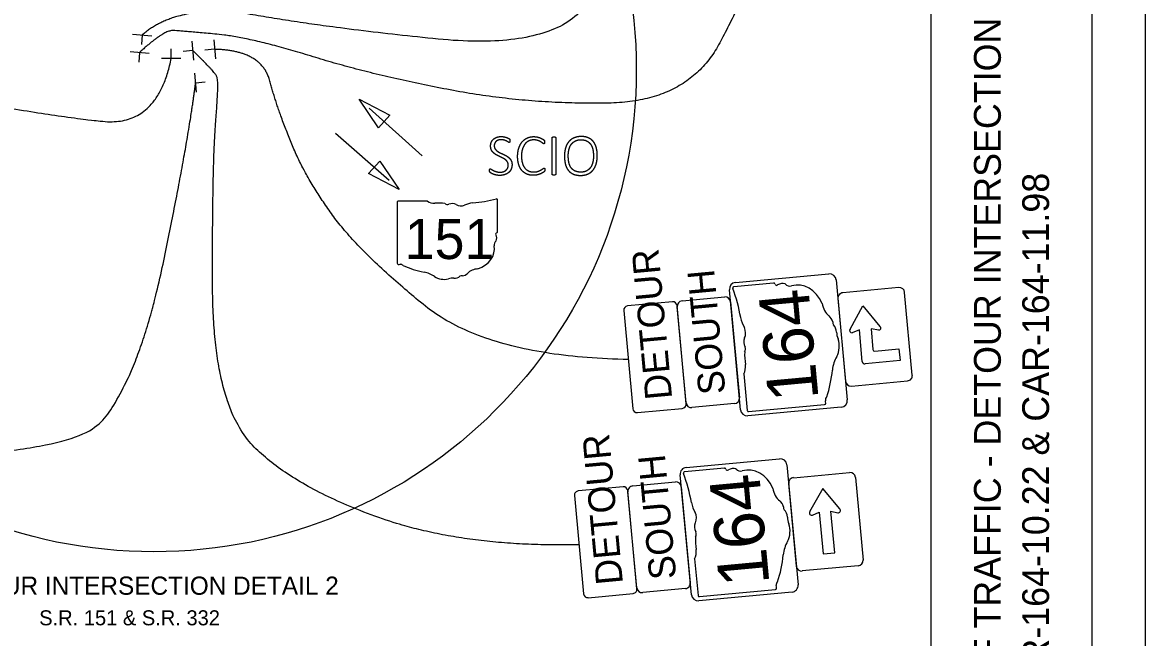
# Model space of a CAD drawing. Extents: x -740 to 1519, y 0 to 440.
# Drawn here: x 470.5 to 680, y 222.2 to 337.1 of the extents above; entities that cross this region are included whole.
import ezdxf

# ---------------------------------------------------------------- set-up
doc = ezdxf.new("R2010")
doc.units = 0
for name, color, linetype in [('Default', 7, 'Continuous'), ('GM_X_County_Road_Text', 7, 'Continuous'), ('GM_X_Major_Lake', 7, 'Continuous'), ('GM_X_Minor_Lake', 7, 'Continuous'), ('GM_X_Minor_River', 7, 'Continuous'), ('GM_X_Section', 7, 'Continuous'), ('SH_Border', 7, 'Continuous'), ('SH_Cut_Line', 7, 'Continuous'), ('SH_Data', 7, 'Continuous')]:
    doc.layers.add(name, color=color, linetype=linetype)

msp = doc.modelspace()

# ---------------------------------------------------------------- linework, layer by layer
at = {"layer": 'Default'}
for p, q in [((535.17, 321.09), (545.07, 312.19)), ((538.91, 307.54), (528.91, 316.31))]:
    msp.add_line(p, q, dxfattribs=at)
for points in [[(536.91, 317.42), (533.32, 322.76), (539, 319.74)], [(537.13, 311.18), (540.79, 305.89), (535.07, 308.84)]]:
    msp.add_lwpolyline(points, close=True, dxfattribs=at)
at = {"layer": 'GM_X_County_Road_Text'}
for p, q in [((559.13, 298.01), (559.13, 303.96)), ((540.38, 303.49), (540.38, 292.1)), ((546.06, 303.68), (540.56, 303.68)), ((559.13, 298.01), (559.13, 298.01))]:
    msp.add_line(p, q, dxfattribs=at)
for centre, major_axis, start_param, end_param in [((552.45, 319.2), (19.88, 0), 4.814394, 5.042369), ((558.92, 303.99), (0.209, 0), 6.141152, 7.989035), ((540.59, 303.51), (0.217, 0), 1.712693, 3.28349), ((547.36, 305), (2.11, 0), 4.042523, 4.731795), ((548.06, 297.29), (7.56, 0), 1.404758, 1.657858), ((549.78, 303.57), (0.608, 0), 3.836095, 5.185415), ((550.67, 302.25), (1.26, 0), 0.950623, 2.079405), ((552.3, 304.06), (1.52, 0), 4.081561, 5.145723), ((554.99, 300.2), (4, 0), 1.699011, 2.107814), ((559.08, 297.57), (0.323, 0), 1.883978, 3.671073), ((558.91, 297.98), (0.223, 0), 5.05454, 6.418171), ((559.88, 295.52), (1.41, 0), 2.387724, 3.262537), ((557.03, 296.82), (1.94, 0), 5.934695, 6.695948), ((553.56, 294.76), (4.97, 0), 5.101752, 6.440018), ((540.6, 292.08), (0.219, 0), 3.00124, 4.508301), ((540.63, 293.24), (1.67, 0), 4.665946, 4.897461), ((540.97, 291.44), (0.603, 0), 0.519207, 1.627899), ((548.59, 301.67), (14.36, 0), 4.195997, 4.488961), ((544.3, 286.99), (4.49, 0), 0.823519, 1.323587), ((549.16, 291.39), (2.85, 0), 4.026481, 4.996735), ((550.81, 287.45), (2.34, 0), 1.495662, 1.94098), ((551.02, 290.53), (1.52, 0), 4.691044, 5.507374), ((552.39, 289.43), (0.428, 0), 1.147584, 2.315152), ((552.21, 291), (1.61, 0), 4.937069, 5.64225), ((555.66, 288.9), (2.72, 0), 1.647645, 2.488434)]:
    msp.add_ellipse(centre, major_axis=major_axis, ratio=0.8, start_param=start_param, end_param=end_param, dxfattribs=at)
at = {"layer": 'GM_X_Major_Lake'}
for p, q in [((569.3, 308.71), (569.3, 315.56)), ((569.96, 315.56), (569.96, 308.71)), ((577.72, 312.22), (577.72, 312.22)), ((561.82, 310.52), (561.82, 310.52)), ((577.01, 312.16), (577.01, 312.16)), ((567.94, 309.57), (567.94, 309.57))]:
    msp.add_line(p, q, dxfattribs=at)
for points in [[(557.82, 314.01), (557.82, 314.42), (557.97, 314.75)], [(557.97, 314.75), (558.12, 315.07), (558.38, 315.3)], [(558.38, 315.3), (558.65, 315.53), (559.03, 315.65)], [(558.58, 314.49), (558.5, 314.29), (558.5, 314.06)], [(558.82, 314.84), (558.66, 314.69), (558.58, 314.49)], [(559.22, 315.08), (558.98, 314.99), (558.82, 314.84)], [(559.03, 315.65), (559.4, 315.77), (559.85, 315.77)], [(559.78, 315.17), (559.46, 315.17), (559.22, 315.08)], [(560.36, 315.09), (560.11, 315.17), (559.78, 315.17)], [(559.85, 315.77), (560.07, 315.77), (560.3, 315.72)], [(560.3, 315.72), (560.53, 315.68), (560.74, 315.61)], [(560.81, 314.91), (560.62, 315.01), (560.36, 315.09)], [(560.74, 315.61), (560.94, 315.54), (561.1, 315.46)], [(561.11, 314.73), (560.99, 314.81), (560.81, 314.91)], [(561.1, 315.46), (561.26, 315.38), (561.32, 315.33)], [(561.3, 314.65), (561.24, 314.65), (561.11, 314.73)], [(561.35, 314.68), (561.33, 314.65), (561.3, 314.65)], [(561.32, 315.33), (561.37, 315.27), (561.38, 315.25)], [(561.4, 314.74), (561.38, 314.7), (561.35, 314.68)], [(561.38, 315.25), (561.4, 315.22), (561.41, 315.19)], [(561.42, 314.84), (561.41, 314.78), (561.4, 314.74)], [(561.41, 315.19), (561.42, 315.15), (561.42, 315.1)], [(561.42, 315.1), (561.43, 315.04), (561.43, 314.97)], [(561.43, 314.97), (561.43, 314.89), (561.42, 314.84)], [(563.08, 313.6), (563.3, 314.28), (563.7, 314.76)], [(563.7, 314.76), (564.09, 315.24), (564.65, 315.49)], [(564.21, 314.35), (563.92, 313.97), (563.75, 313.4)], [(564.93, 314.94), (564.51, 314.74), (564.21, 314.35)], [(564.65, 315.49), (565.2, 315.75), (565.87, 315.75)], [(565.84, 315.14), (565.34, 315.14), (564.93, 314.94)], [(566.62, 315.03), (566.29, 315.14), (565.84, 315.14)], [(565.87, 315.75), (566.19, 315.75), (566.49, 315.69)], [(566.49, 315.69), (566.78, 315.63), (567.04, 315.53)], [(567.17, 314.78), (566.95, 314.92), (566.62, 315.03)], [(567.04, 315.53), (567.29, 315.44), (567.49, 315.32)], [(567.54, 314.53), (567.4, 314.64), (567.17, 314.78)], [(567.49, 315.32), (567.69, 315.2), (567.76, 315.13)], [(567.76, 314.42), (567.68, 314.42), (567.54, 314.53)], [(567.76, 315.13), (567.83, 315.05), (567.85, 315.02)], [(567.82, 314.44), (567.79, 314.42), (567.76, 314.42)], [(567.87, 314.5), (567.85, 314.46), (567.82, 314.44)], [(567.85, 315.02), (567.87, 314.99), (567.88, 314.95)], [(567.9, 314.6), (567.89, 314.55), (567.87, 314.5)], [(567.88, 314.95), (567.89, 314.91), (567.9, 314.85)], [(567.9, 314.85), (567.9, 314.8), (567.9, 314.74)], [(567.9, 314.74), (567.9, 314.66), (567.9, 314.6)], [(569.3, 315.56), (569.3, 315.6), (569.32, 315.63)], [(569.32, 315.63), (569.34, 315.65), (569.38, 315.67)], [(569.38, 315.67), (569.42, 315.69), (569.48, 315.7)], [(569.48, 315.7), (569.54, 315.71), (569.63, 315.71)], [(569.63, 315.71), (569.73, 315.71), (569.79, 315.7)], [(569.79, 315.7), (569.86, 315.69), (569.89, 315.67)], [(569.89, 315.67), (569.93, 315.65), (569.95, 315.63)], [(569.95, 315.63), (569.96, 315.6), (569.96, 315.56)], [(572.37, 314.76), (571.98, 314.29), (571.79, 313.61)], [(573.35, 315.5), (572.76, 315.24), (572.37, 314.76)], [(572.43, 313.31), (572.56, 313.86), (572.84, 314.27)], [(572.84, 314.27), (573.12, 314.68), (573.57, 314.92)], [(574.73, 315.77), (573.94, 315.77), (573.35, 315.5)], [(573.57, 314.92), (574.02, 315.17), (574.68, 315.17)], [(574.68, 315.17), (575.34, 315.17), (575.78, 314.93)], [(576.06, 315.52), (575.5, 315.77), (574.73, 315.77)], [(575.78, 314.93), (576.23, 314.7), (576.5, 314.3)], [(577, 314.82), (576.63, 315.28), (576.06, 315.52)], [(576.5, 314.3), (576.77, 313.89), (576.89, 313.34)], [(577.54, 313.7), (577.36, 314.36), (577, 314.82)], [(557.96, 313.29), (557.82, 313.59), (557.82, 314.01)], [(558.34, 312.75), (558.1, 312.98), (557.96, 313.29)], [(558.86, 312.36), (558.57, 312.53), (558.34, 312.75)], [(558.5, 314.06), (558.5, 313.73), (558.64, 313.5)], [(558.64, 313.5), (558.78, 313.26), (559.02, 313.08)], [(559.47, 312.04), (559.16, 312.19), (558.86, 312.36)], [(559.02, 313.08), (559.25, 312.9), (559.55, 312.76)], [(559.55, 312.76), (559.85, 312.61), (560.16, 312.47)], [(560.16, 312.47), (560.47, 312.33), (560.76, 312.16)], [(562.86, 312.05), (562.86, 312.91), (563.08, 313.6)], [(563.75, 313.4), (563.58, 312.83), (563.58, 312.09)], [(571.79, 313.61), (571.6, 312.93), (571.6, 312.1)], [(572.31, 312.16), (572.31, 312.77), (572.43, 313.31)], [(576.89, 313.34), (577.01, 312.79), (577.01, 312.16)], [(577.53, 310.69), (577.72, 311.37), (577.72, 312.22)], [(577.72, 312.22), (577.72, 313.05), (577.54, 313.7)], [(560.07, 311.75), (559.78, 311.9), (559.47, 312.04)], [(560.6, 311.43), (560.37, 311.61), (560.07, 311.75)], [(560.97, 311.02), (560.83, 311.25), (560.6, 311.43)], [(560.76, 312.16), (561.06, 311.99), (561.3, 311.77)], [(561.11, 310.46), (561.11, 310.78), (560.97, 311.02)], [(561, 309.89), (561.11, 310.14), (561.11, 310.46)], [(561.3, 311.77), (561.53, 311.54), (561.67, 311.24)], [(561.82, 310.52), (561.82, 310.05), (561.65, 309.68)], [(561.67, 311.24), (561.82, 310.93), (561.82, 310.52)], [(563.07, 310.55), (562.86, 311.2), (562.86, 312.05)], [(563.65, 309.44), (563.27, 309.89), (563.07, 310.55)], [(563.58, 312.09), (563.58, 311.39), (563.74, 310.84)], [(563.74, 310.84), (563.89, 310.29), (564.18, 309.92)], [(571.6, 312.1), (571.6, 311.27), (571.77, 310.6)], [(571.77, 310.6), (571.94, 309.93), (572.31, 309.47)], [(572.42, 310.96), (572.31, 311.52), (572.31, 312.16)], [(572.8, 310), (572.54, 310.41), (572.42, 310.96)], [(576.89, 311.01), (576.77, 310.46), (576.49, 310.04)], [(577.01, 312.16), (577.01, 311.56), (576.89, 311.01)], [(576.94, 309.52), (577.33, 310), (577.53, 310.69)], [(557.62, 309.41), (557.62, 309.51), (557.63, 309.57)], [(557.65, 309.2), (557.62, 309.29), (557.62, 309.41)], [(557.63, 309.57), (557.64, 309.63), (557.66, 309.67)], [(557.74, 309.06), (557.68, 309.12), (557.65, 309.2)], [(557.66, 309.67), (557.68, 309.7), (557.71, 309.72)], [(557.71, 309.72), (557.74, 309.73), (557.77, 309.73)], [(557.96, 308.9), (557.8, 308.99), (557.74, 309.06)], [(557.77, 309.73), (557.85, 309.73), (557.99, 309.64)], [(558.35, 308.72), (558.12, 308.81), (557.96, 308.9)], [(557.99, 309.64), (558.13, 309.54), (558.35, 309.43)], [(558.35, 309.43), (558.57, 309.32), (558.88, 309.22)], [(558.89, 308.57), (558.59, 308.64), (558.35, 308.72)], [(558.88, 309.22), (559.19, 309.12), (559.6, 309.12)], [(559.53, 308.51), (559.19, 308.51), (558.89, 308.57)], [(560.44, 308.65), (560.02, 308.51), (559.53, 308.51)], [(559.6, 309.12), (559.93, 309.12), (560.21, 309.21)], [(560.21, 309.21), (560.49, 309.3), (560.69, 309.47)], [(561.17, 309.04), (560.86, 308.78), (560.44, 308.65)], [(560.69, 309.47), (560.89, 309.64), (561, 309.89)], [(561.65, 309.68), (561.48, 309.3), (561.17, 309.04)], [(564.57, 308.76), (564.03, 309), (563.65, 309.44)], [(564.18, 309.92), (564.47, 309.55), (564.89, 309.35)], [(565.78, 308.53), (565.11, 308.53), (564.57, 308.76)], [(564.89, 309.35), (565.32, 309.15), (565.86, 309.15)], [(566.54, 308.61), (566.19, 308.53), (565.78, 308.53)], [(565.86, 309.15), (566.3, 309.15), (566.63, 309.26)], [(567.15, 308.81), (566.88, 308.7), (566.54, 308.61)], [(566.63, 309.26), (566.96, 309.38), (567.2, 309.51)], [(567.59, 309.04), (567.41, 308.93), (567.15, 308.81)], [(567.2, 309.51), (567.43, 309.65), (567.58, 309.76)], [(567.58, 309.76), (567.73, 309.87), (567.82, 309.87)], [(567.81, 309.21), (567.76, 309.16), (567.59, 309.04)], [(567.89, 309.3), (567.87, 309.26), (567.81, 309.21)], [(567.82, 309.87), (567.85, 309.87), (567.87, 309.86)], [(567.87, 309.86), (567.89, 309.84), (567.91, 309.81)], [(567.92, 309.37), (567.9, 309.33), (567.89, 309.3)], [(567.91, 309.81), (567.92, 309.77), (567.93, 309.71)], [(567.93, 309.46), (567.93, 309.41), (567.92, 309.37)], [(567.93, 309.71), (567.94, 309.65), (567.94, 309.57)], [(567.94, 309.57), (567.94, 309.51), (567.93, 309.46)], [(569.31, 308.65), (569.3, 308.68), (569.3, 308.71)], [(569.37, 308.61), (569.33, 308.63), (569.31, 308.65)], [(569.47, 308.58), (569.41, 308.59), (569.37, 308.61)], [(569.63, 308.57), (569.54, 308.57), (569.47, 308.58)], [(569.79, 308.58), (569.73, 308.57), (569.63, 308.57)], [(569.89, 308.61), (569.86, 308.59), (569.79, 308.58)], [(569.95, 308.65), (569.93, 308.63), (569.89, 308.61)], [(569.96, 308.71), (569.96, 308.68), (569.95, 308.65)], [(572.31, 309.47), (572.67, 309.01), (573.24, 308.76)], [(573.52, 309.36), (573.07, 309.59), (572.8, 310)], [(573.24, 308.76), (573.8, 308.51), (574.59, 308.51)], [(574.64, 309.12), (573.97, 309.12), (573.52, 309.36)], [(574.59, 308.51), (575.38, 308.51), (575.97, 308.77)], [(575.76, 309.37), (575.3, 309.12), (574.64, 309.12)], [(576.49, 310.04), (576.21, 309.62), (575.76, 309.37)], [(575.97, 308.77), (576.56, 309.04), (576.94, 309.52)]]:
    msp.add_open_spline(points, degree=2, dxfattribs=at)
at = {"layer": 'GM_X_Minor_Lake'}
for p, q in [((614.34, 252.09), (624.79, 253.06)), ((625.88, 252.15), (627.31, 236.72)), ((614.86, 235.57), (613.43, 251)), ((619.79, 250.09), (617.34, 245.7)), ((622.95, 246.28), (619.79, 250.09)), ((617.87, 245.11), (619.11, 245.63)), ((619.11, 245.63), (619.83, 237.85)), ((622.01, 238.05), (621.29, 245.83)), ((621.29, 245.83), (622.6, 245.55)), ((619.83, 237.85), (622.01, 238.05)), ((626.4, 235.63), (615.95, 234.67))]:
    msp.add_line(p, q, dxfattribs=at)
for centre, radius, start, end in [((614.43, 251.1), 1, 95.2824, 185.2824), ((624.88, 252.06), 1, 5.2824, 95.2824), ((617.71, 245.5), 0.417, 150.6936, 292.487), ((622.68, 245.96), 0.417, 258.0778, 50.2919), ((615.85, 235.66), 1, 185.2824, 275.2824), ((626.31, 236.63), 1, 275.2824, 5.2824)]:
    msp.add_arc(centre, radius, start, end, dxfattribs=at)
at = {"layer": 'GM_X_Minor_River'}
for p, q in [((491.04, 334.89), (494.63, 334.58)), ((492.83, 334.73), (492.68, 332.94)), ((502.1, 333.59), (502.41, 330.01)), ((506.16, 333.84), (506.47, 330.26)), ((490.56, 331.63), (494.15, 331.32)), ((492.35, 331.47), (492.2, 329.68)), ((498.24, 330.34), (498.25, 332.14)), ((502.26, 331.8), (500.46, 331.65)), ((506.32, 332.05), (504.52, 331.89)), ((500.04, 330.33), (496.44, 330.35)), ((502.96, 324.02), (502.63, 327.61)), ((502.79, 325.82), (504.59, 325.98)), ((610.62, 288.4), (603.21, 287.71)), ((610.62, 288.4), (610.62, 288.4)), ((633.97, 287.58), (623.51, 286.61)), ((593.53, 285.09), (601.5, 285.83)), ((622.61, 285.52), (624.05, 270.09)), ((636.49, 271.25), (635.06, 286.68)), ((594.28, 266.08), (592.63, 284.01)), ((602.58, 284.93), (604.24, 267)), ((624.89, 279.82), (627.29, 284.14)), ((627.29, 284.14), (630.45, 280.33)), ((626.61, 279.68), (625.25, 279.13)), ((627.16, 273.77), (626.61, 279.68)), ((630.22, 279.6), (628.79, 279.88)), ((628.79, 279.88), (629.15, 275.99)), ((629.49, 275.71), (634, 276.13)), ((634, 276.13), (634.2, 273.95)), ((627.16, 273.77), (627.16, 273.77)), ((634.2, 273.95), (627.67, 273.34)), ((605.06, 271.47), (605.69, 264.64)), ((625.14, 269.19), (635.59, 270.16)), ((603.34, 265.91), (595.37, 265.18)), ((605.96, 264.43), (620.13, 265.74)), ((601.43, 253.87), (594.01, 253.18)), ((601.42, 253.87), (601.43, 253.87)), ((585.11, 231.54), (583.44, 249.46)), ((584.34, 250.55), (592.31, 251.3)), ((593.4, 250.39), (595.07, 232.47)), ((595.88, 236.94), (596.52, 230.11)), ((594.16, 231.38), (586.2, 230.64)), ((596.78, 229.9), (610.95, 231.22))]:
    msp.add_line(p, q, dxfattribs=at)
for points in [[(603.51, 288.53), (620.93, 290.14)], [(604.45, 264.76), (602.38, 287.17)], [(622.29, 289.01), (624.36, 266.6)], [(582.65, 283.28), (584.35, 264.96)], [(591.74, 284.93), (583.37, 284.15)], [(594.3, 265.88), (592.61, 284.2)], [(585.22, 264.24), (593.58, 265.01)], [(623.23, 265.24), (605.81, 263.63)], [(594.32, 253.99), (611.74, 255.62)], [(613.1, 254.49), (615.19, 232.09)], [(595.28, 230.23), (593.19, 252.63)], [(582.55, 250.39), (574.19, 249.61)], [(585.13, 231.34), (583.42, 249.66)], [(573.46, 248.74), (575.17, 230.41)], [(576.04, 229.69), (584.41, 230.47)], [(614.06, 230.72), (596.64, 229.1)]]:
    msp.add_lwpolyline(points, dxfattribs=at)
for centre, radius, start, end in [((621.05, 288.89), 1.25, 5.2824, 95.2824), ((603.62, 287.28), 1.25, 95.2824, 185.2824), ((634.06, 286.59), 1, 5.3248, 95.3248), ((593.62, 284.1), 1, 95.2824, 185.2824), ((601.59, 284.83), 1, 5.2824, 95.2824), ((623.61, 285.61), 1, 95.3248, 185.3248), ((583.45, 283.36), 0.8, 95.2824, 185.2824), ((591.81, 284.13), 0.8, 5.2824, 95.2824), ((625.21, 279.55), 0.417, 140.3249, 275.3231), ((630.19, 280.01), 0.417, 275.3231, 50.3246), ((629.46, 276.02), 0.312, 185.3248, 275.3248), ((627.63, 273.81), 0.469, 185.3248, 275.3248), ((635.5, 271.16), 1, 275.3248, 5.3248), ((625.04, 270.18), 1, 185.3248, 275.3248), ((603.25, 266.91), 1, 275.2824, 5.2824), ((623.12, 266.49), 1.25, 275.2824, 5.2824), ((585.14, 265.04), 0.8, 185.2824, 275.2824), ((593.51, 265.81), 0.8, 275.2824, 5.2824), ((595.28, 266.17), 1, 185.2824, 275.2824), ((605.69, 264.88), 1.25, 185.2824, 275.2824), ((611.86, 254.37), 1.25, 5.3248, 95.3248), ((594.43, 252.75), 1.25, 95.3248, 185.3248), ((574.26, 248.81), 0.8, 95.3248, 185.3248), ((582.62, 249.59), 0.8, 5.3248, 95.3248), ((584.44, 249.56), 1, 95.3248, 185.3248), ((592.4, 250.3), 1, 5.3248, 95.3248), ((584.33, 231.27), 0.8, 275.3248, 5.3248), ((586.11, 231.63), 1, 185.3248, 275.3248), ((594.07, 232.38), 1, 275.3248, 5.3248), ((613.94, 231.97), 1.25, 275.3248, 5.3248), ((575.97, 230.49), 0.8, 185.3248, 275.3248), ((596.52, 230.35), 1.25, 185.3248, 275.3248)]:
    msp.add_arc(centre, radius, start, end, dxfattribs=at)
for centre, major_axis, start_param, end_param in [((603.2, 287.45), (-0.024, 0.26), 6.141152, 7.989035), ((585.01, 277.65), (-2.29, 24.75), 4.814394, 5.042369), ((610.67, 288.12), (-0.026, 0.278), 5.05454, 6.418171), ((611.17, 288.39), (-0.037, 0.402), 1.883978, 3.671073), ((612.34, 285.92), (-0.22, 2.41), 5.934695, 6.695948), ((613.63, 289.62), (-0.16, 1.76), 2.387724, 3.262537), ((615.3, 281.84), (-0.57, 6.19), 5.101752, 6.440018), ((622.35, 285.13), (-0.31, 3.39), 1.647645, 2.488434), ((608.36, 282.99), (-0.46, 4.98), 1.699011, 2.107814), ((620.14, 280.59), (-0.18, 2), 4.937069, 5.64225), ((622.07, 281), (-0.049, 0.532), 1.147584, 2.315152), ((603.87, 279.2), (-0.17, 1.89), 4.081561, 5.145723), ((620.85, 279.16), (-0.17, 1.89), 4.691044, 5.507374), ((624.71, 279.26), (-0.27, 2.92), 1.495662, 1.94098), ((606.31, 277.38), (-0.15, 1.57), 0.950623, 2.079405), ((620.01, 276.75), (-0.33, 3.55), 4.026481, 4.996735), ((612.79, 274.7), (-0.87, 9.41), 1.404758, 1.657858), ((604.77, 276.12), (-0.07, 0.757), 3.836095, 5.185415), ((626.04, 271.21), (-0.52, 5.59), 0.823519, 1.323587), ((603.27, 272.95), (-0.24, 2.62), 4.042523, 4.731795), ((607.27, 274.85), (-1.65, 17.87), 4.195997, 4.488961), ((620.88, 266.55), (-0.069, 0.751), 0.519207, 1.627899), ((618.68, 265.92), (-0.19, 2.08), 4.665946, 4.897461), ((605.9, 264.69), (-0.025, 0.27), 1.712693, 3.28349), ((620.13, 266.01), (-0.025, 0.273), 3.00124, 4.508301), ((601.48, 253.6), (-0.026, 0.278), 5.05454, 6.418171), ((601.98, 253.86), (-0.037, 0.402), 1.883978, 3.671073), ((603.15, 251.39), (-0.22, 2.41), 5.934695, 6.695948), ((604.44, 255.09), (-0.16, 1.76), 2.387724, 3.262537), ((606.12, 247.32), (-0.58, 6.19), 5.101752, 6.440018), ((594.01, 252.92), (-0.024, 0.26), 6.141152, 7.989035), ((575.82, 243.1), (-2.31, 24.75), 4.814394, 5.042369), ((613.16, 250.61), (-0.32, 3.39), 1.647645, 2.488434), ((599.17, 248.46), (-0.46, 4.98), 1.699011, 2.107814), ((610.95, 246.07), (-0.19, 2), 4.937069, 5.64225), ((594.69, 244.67), (-0.18, 1.89), 4.081561, 5.145723), ((612.88, 246.48), (-0.05, 0.532), 1.147584, 2.315152), ((611.67, 244.64), (-0.18, 1.89), 4.691044, 5.507374), ((597.12, 242.85), (-0.15, 1.57), 0.950623, 2.079405), ((615.53, 244.74), (-0.27, 2.92), 1.495662, 1.94098), ((610.82, 242.23), (-0.33, 3.55), 4.026481, 4.996735), ((603.6, 240.18), (-0.88, 9.41), 1.404758, 1.657858), ((595.59, 241.59), (-0.071, 0.756), 3.836095, 5.185415), ((616.86, 236.7), (-0.52, 5.59), 0.823519, 1.323587), ((594.09, 238.41), (-0.24, 2.62), 4.042523, 4.731795), ((598.09, 240.32), (-1.67, 17.87), 4.195997, 4.488961), ((611.7, 232.03), (-0.07, 0.75), 0.519207, 1.627899), ((610.96, 231.49), (-0.025, 0.273), 3.00124, 4.508301), ((609.51, 231.4), (-0.19, 2.08), 4.665946, 4.897461), ((596.73, 230.16), (-0.025, 0.27), 1.712693, 3.28349)]:
    msp.add_ellipse(centre, major_axis=major_axis, ratio=0.8, start_param=start_param, end_param=end_param, dxfattribs=at)
at = {"layer": 'SH_Border'}
msp.add_line((640, 10), (640, 430), dxfattribs=at)
msp.add_lwpolyline([(30, 430), (670, 430), (670, 10), (30, 10)], close=True, dxfattribs=at)
at = {"layer": 'SH_Cut_Line'}
msp.add_lwpolyline([(0, 0), (680, 0), (680, 440), (0, 440)], close=True, dxfattribs=at)
at = {"layer": 'SH_Data'}
msp.add_circle((495, 328.25), 90, dxfattribs=at)
for points in [[(587.4, 375.37), (584.62, 359.99), (581.97, 346.71), (567.83, 331.99), (528.05, 335.95), (499.96, 340.86), (492.83, 334.73)], [(378.35, 365.83), (385, 348.06), (402, 338.57), (434.58, 327.18), (475.36, 319.62), (495.67, 317.59), (498.24, 330.34)], [(616.69, 366.37), (606.43, 344.47), (594.88, 322.35), (565.19, 321.69), (536.27, 327.08), (513, 334.3), (500.41, 335.45), (496.86, 335.66), (492.35, 331.47)], [(574.32, 239.58), (552.66, 239.06), (521.3, 250.21), (506, 265.56), (505.9, 310.65), (507.14, 325.83), (506.46, 327.8), (502.26, 331.8)], [(583.5, 274.12), (557.22, 274.67), (533.5, 294.02), (523.37, 307.92), (518.09, 320.75), (515.07, 331.85), (506.32, 332.05)], [(413.82, 255.38), (478.14, 254.29), (492.33, 270.79), (501.43, 314.73), (502.79, 325.82)]]:
    msp.add_open_spline(points, degree=2, dxfattribs=at)

# ---------------------------------------------------------------- texts
at = {"layer": 'GM_X_County_Road_Text'}
msp.add_text('151', height=7.5, dxfattribs=at).set_placement((541.79, 292.9))
at = {"layer": 'GM_X_Minor_River'}
for s, height, rotation, p in [('DETOUR', 5, 95.2824, (591.7, 266.88)), ('SOUTH', 5, 95.2824, (601.65, 267.85)), ('164', 9.375, 95.2824, (619.02, 266.79)), ('DETOUR', 5, 95.3248, (582.52, 232.34)), ('SOUTH', 5, 95.3248, (592.48, 233.32)), ('164', 9.375, 95.3248, (609.85, 232.27))]:
    msp.add_text(s, height=height, rotation=rotation, dxfattribs=at).set_placement(p)
at = {"layer": 'GM_X_Section'}
for s, height, p in [('DETOUR INTERSECTION DETAIL 2', 3.4, (454.21, 230.23)), ('S.R. 151 & S.R. 332', 2.8, (473.61, 224.53))]:
    msp.add_text(s, height=height, dxfattribs=at).set_placement(p)
at = {"layer": 'SH_Data'}
for s, p in [('MAINTENANCE OF TRAFFIC - DETOUR INTERSECTION DETAILS', (653, 162.26)), ('CAR-164-10.22 & CAR-164-11.98', (662, 207.91))]:
    msp.add_text(s, height=5, rotation=90, dxfattribs=at).set_placement(p)

doc.saveas('drawing.dxf')
